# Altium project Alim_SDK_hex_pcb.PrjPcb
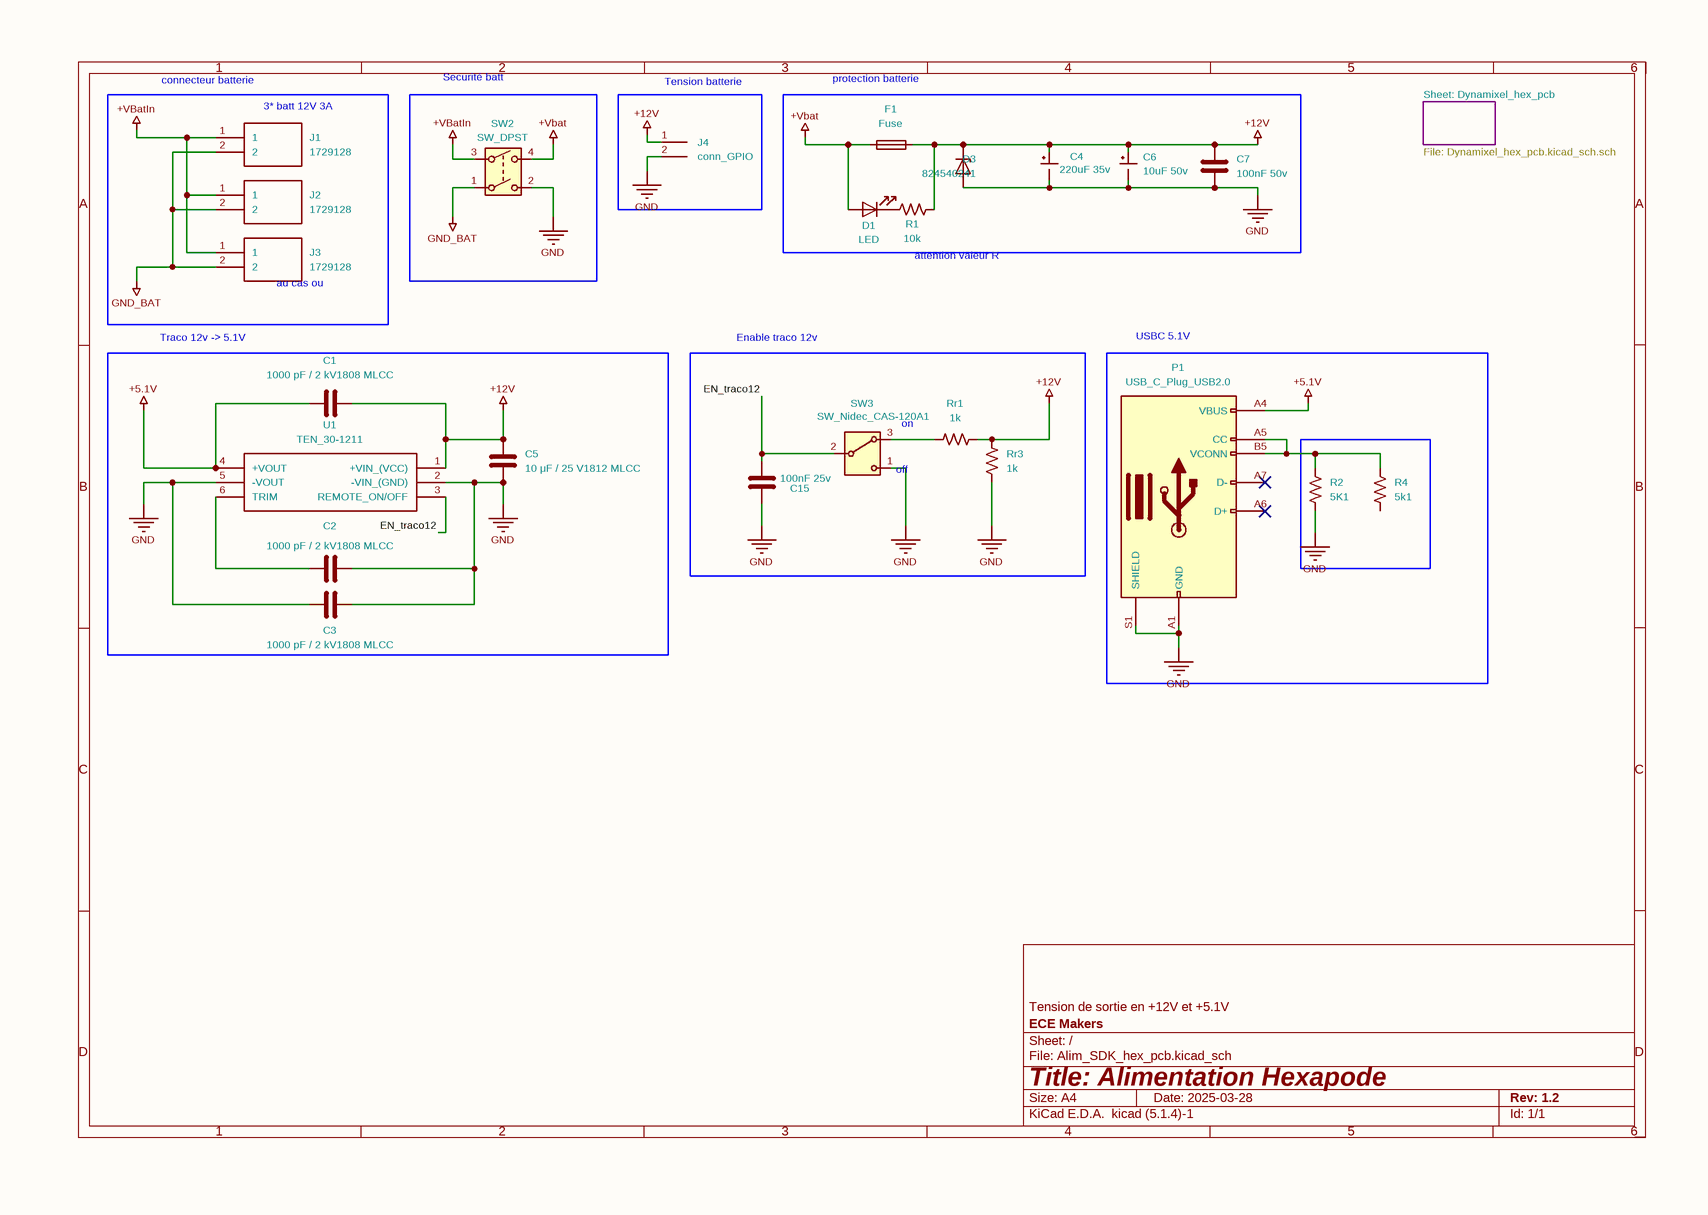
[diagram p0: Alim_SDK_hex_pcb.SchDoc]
2 sheets, 41 parts. Net scope: global (net labels, ports and power ports of the same name join across sheets).
Sheets:
  Alim_SDK_hex_pcb.SchDoc
    Dynamixel_hex_pcb = Dynamixel_hex_pcb.SchDoc

## Sheet Alim_SDK_hex_pcb.SchDoc
size 297 x 209 mm

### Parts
C1  1000 pF / 2 kV1808 MLCC  [C_0603_1608Metric]
C2  1000 pF / 2 kV1808 MLCC  [C_0603_1608Metric]
C3  1000 pF / 2 kV1808 MLCC  [C_0603_1608Metric]
C4  220uF 35v  [CP_Wurth_WCAP-HSG5-D8L10.5]
C5  10 μF / 25 V1812 MLCC  [C_0603_1608Metric]
C6  10uF 50v  [CP_Wurth_WCAP-HSG5-D5L5.8]
C7  100nF 50v  [C_0603_1608Metric]
C15  100nF 25v  [C_0603_1608Metric]
D1  LED  [LED_0603_1608Metric_Pad1.05x0.95mm_HandSolder]
D3  824540241  [D_0603_1608Metric]
F1  Fuse
J1  1729128  [691250610002]
J2  1729128  [691250610002]
J3  1729128  [691250610002]
J4  conn_GPIO  [PinHeader_1x02_P2.54mm_Vertical]
P1  USB_C_Plug_USB2.0
R1  10k  [R_0603_1608Metric_Pad0.98x0.95mm_HandSolder]
R2  5K1  [R_0201_0603Metric]
R4  5k1  [R_0201_0603Metric]
Rr1  1k  [R_0201_0603Metric]
Rr3  1k  [R_0201_0603Metric]
SW2  SW_DPST
SW3  SW_Nidec_CAS-120A1  [SW_Slide_SPDT_Straight_CK_OS102011MS2Q]
U1  TEN_30-1211  [Converter_DCDC_TRACO_THN30-xxxx_THT]

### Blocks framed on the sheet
Securité batt: SW2
Tension batterie: J4
protection batterie: C4 C6 C7 D1 D3 F1 R1
Traco 12v -> 5.1V: C1-C3 C5 U1
USBC 5.1V /: P1 R2 R4

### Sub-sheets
Dynamixel_hex_pcb = Dynamixel_hex_pcb.SchDoc: no entries

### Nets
+5.1V: C1.1 P1.A4(VBUS) U1.4(+VOUT)
+12V: C1.2 C4.1 C5.1 C6.1 C7.1 D3.1(K) F1.2 J4.1(Pin_1) R1.2 Rr1.2 Rr3.2 U1.1(+VIN_(VCC))
+Vbat: D1.2(A) F1.1 SW2.4
+VBatIn: J1.1 J2.1 J3.1 SW2.3
GND: C2.2 C3.1 C3.2 C4.2 C5.2 C6.2 C7.2 C15.2 D3.2(A) J4.2(Pin_2) P1.A1(GND) P1.S1(SHIELD) R2.2 Rr3.1 SW2.2 SW3.1(C) U1.2(-VIN_(GND)) U1.5(-VOUT)
GND_BAT: J1.2 J2.2 J3.2 SW2.1
EN_traco12: C15.1 SW3.2(B) U1.3(REMOTE_ON/OFF)
NetC2_1: C2.1 U1.6(TRIM)
NetD1_1: D1.1(K) R1.1
NetP1_A5: P1.A5(CC) P1.B5(VCONN) R2.1 R4.1
NetRr1_1: Rr1.1 SW3.3(A)

Not connected (* = marked no-connect by the designer): P1 A6(D+)* A7(D-)* A9(VBUS) A12(GND) B1(GND) B4(VBUS) B9(VBUS) B12(GND); R4 2

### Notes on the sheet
- (near J1) connecteur batterie
- (near J1) 3* batt 12V 3A
- File: Dynamixel_hex_pcb.kicad_sch.sch
- Sheet: Dynamixel_hex_pcb
- (near J3) au cas ou
- attention valeur R
- Enable traco 12v
- on
- (near SW3) off

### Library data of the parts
C1-C3 C5 C7 C15 = C: Description: Unpolarized capacitor
C4 C6 = C_Polarized_Small_US: Description: Polarized capacitor, small US symbol
D1 = LED: Description: Light emitting diode
D3 = D_Zener: Description: Zener diode
J1-J3 = 1729128: Manufacturer_Name: Phoenix Contact; Description: PCB terminal block, nominal current: 13.5 A, rated voltage (III/2): 400 V, nominal cross section: 1.5 mm?, Number of potentials: 2, Number of rows: 1, Number of positions per row: 2, product range: MKDSN 1,5, pitch: 5.08 mm, connection method: Screw connection with tension sleeve, mounting: Wave soldering, conductor/PCB connection direction: 0 ?, color: green, Pin layout: Linear pinning, Solder pin [P]: 3.5 mm, type of packaging: packed in cardboard
J4 = Conn_01x02_Socket: Description: Generic connector, single row, 01x02, script generated
P1 = USB_C_Plug_USB2.0: Description: USB 2.0-only Type-C Plug connector
R1 R2 R4 Rr1 Rr3 = R_US: Description: Resistor, US symbol
SW2 = SW_DPST: Description: Double Pole Single Throw (DPST) Switch
SW3 = SW_Nidec_CAS-120A1: Description: Switch, single pole double throw
U1 = TEN_30-1211: Manufacturer_Name: Traco Power; Manufacturer_Part_Number: TEN 30-1211; Description: 30 Watt DC/DC converter, industrial, 2:1 input, encapsulated, 2" x 1" metal package

## Sheet Dynamixel_hex_pcb.SchDoc
size 297 x 209 mm
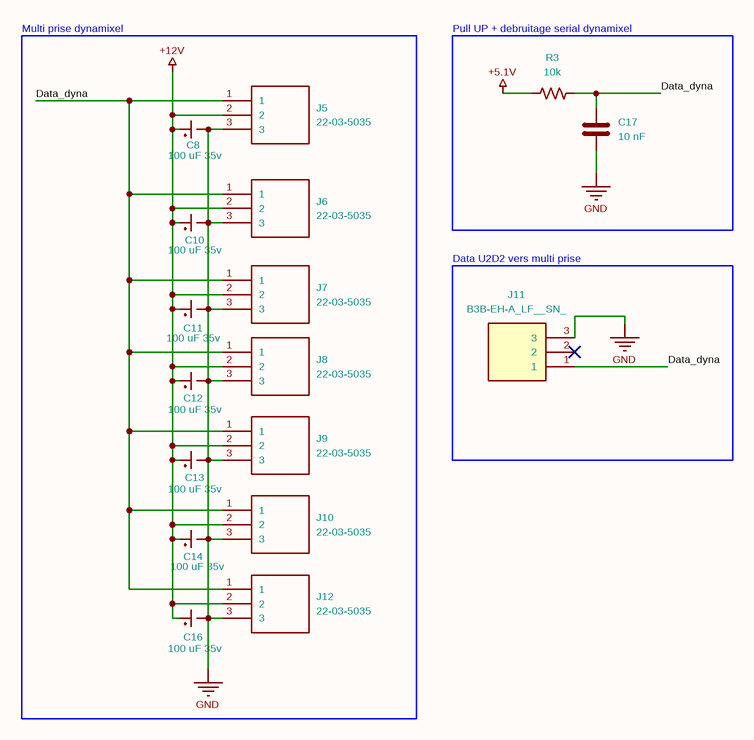
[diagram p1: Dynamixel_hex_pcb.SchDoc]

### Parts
C8  100 uF 35v  [CP_Wurth_WCAP-HSG5-D6.3L7.7]
C10  100 uF 35v  [CP_Wurth_WCAP-HSG5-D6.3L7.7]
C11  100 uF 35v  [CP_Wurth_WCAP-HSG5-D6.3L7.7]
C12  100 uF 35v  [CP_Wurth_WCAP-HSG5-D6.3L7.7]
C13  100 uF 35v  [CP_Wurth_WCAP-HSG5-D6.3L7.7]
C14  100 uF 35v  [CP_Wurth_WCAP-HSG5-D6.3L7.7]
C16  100 uF 35v  [CP_Wurth_WCAP-HSG5-D6.3L7.7]
C17  10 nF  [C_0603_1608Metric]
J5  22-03-5035  [Molex_SPOX_5267-03A_1x03_P2.50mm_Vertical]
J6  22-03-5035  [Molex_SPOX_5267-03A_1x03_P2.50mm_Vertical]
J7  22-03-5035  [Molex_SPOX_5267-03A_1x03_P2.50mm_Vertical]
J8  22-03-5035  [Molex_SPOX_5267-03A_1x03_P2.50mm_Vertical]
J9  22-03-5035  [Molex_SPOX_5267-03A_1x03_P2.50mm_Vertical]
J10  22-03-5035  [Molex_SPOX_5267-03A_1x03_P2.50mm_Vertical]
J11  B3B-EH-A_LF__SN_  [JST_EH_B3B-EH-A_1x03_P2.50mm_Vertical]
J12  22-03-5035  [Molex_SPOX_5267-03A_1x03_P2.50mm_Vertical]
R3  10k  [R_0201_0603Metric]

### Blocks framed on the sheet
Multi prise dynamixel: C8 C10-C14 C16 J5-J10 J12
Pull UP + debruitage serial dynamixel: C17 R3
Data U2D2 vers multi prise: J11

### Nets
+5.1V: R3.1
+12V: C8.1 C10.1 C11.1 C12.1 C13.1 C14.1 C16.1 J5.2 J6.2 J7.2 J8.2 J9.2 J10.2 J12.2
GND: C8.2 C10.2 C11.2 C12.2 C13.2 C14.2 C16.2 C17.2 J5.3 J6.3 J7.3 J8.3 J9.3 J10.3 J11.3 J12.3
Data_dyna: C17.1 J5.1 J6.1 J7.1 J8.1 J9.1 J10.1 J11.1 J12.1 R3.2

Not connected (* = marked no-connect by the designer): J11 2*

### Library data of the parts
C8 C10-C14 C16 = C_Polarized_Small_US
C17 = C
J5-J10 J12 = 22-03-5035: Manufacturer_Name: Molex
J11 = B3B-EH-A_LF__SN_: Manufacturer_Name: JST (JAPAN SOLDERLESS TERMINALS); Manufacturer_Part_Number: B3B-EH-A(LF)(SN)
R3 = R_US

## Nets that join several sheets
+5.1V: Alim_SDK_hex_pcb (C1.1 P1.A4 U1.4), Dynamixel_hex_pcb (R3.1)
+12V: Alim_SDK_hex_pcb (12 pins), Dynamixel_hex_pcb (14 pins)
GND: Alim_SDK_hex_pcb (18 pins), Dynamixel_hex_pcb (16 pins)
